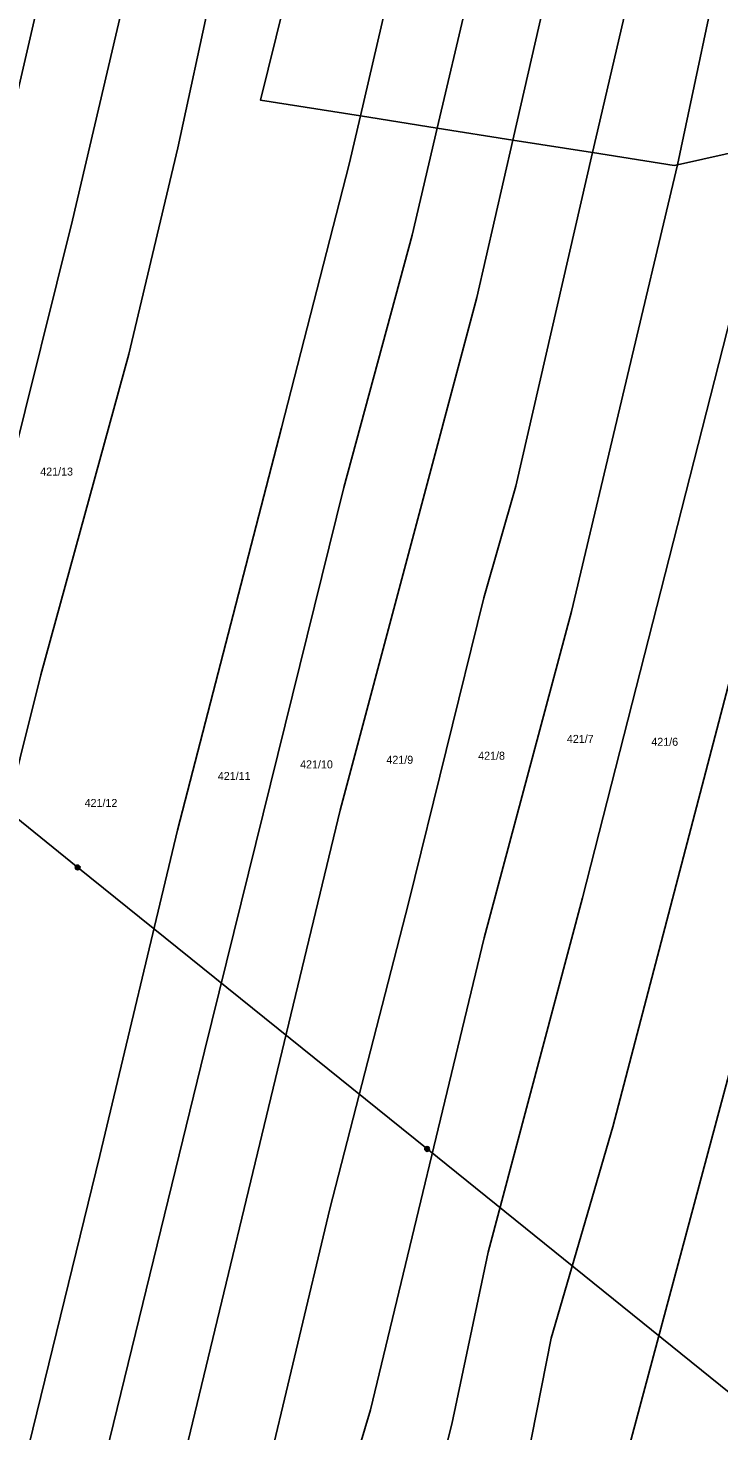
# Model space of a CAD drawing. Extents: x -757266 to -753360, y -1162585 to -1157740.
# Drawn here: x -754320 to -754173.3, y -1161339.7 to -1161041.7 of the extents above; entities that cross this region are included whole.
import ezdxf

# ---------------------------------------------------------------- set-up
doc = ezdxf.new("R2010")
doc.units = 0
for name, color, linetype in [('Hranice parcel', 7, 'Continuous'), ('Parcelní čísla', 7, 'Continuous'), ('Poz předměty', 7, 'Continuous')]:
    doc.layers.add(name, color=color, linetype=linetype)

msp = doc.modelspace()

# ---------------------------------------------------------------- linework, layer by layer
at = {"layer": 'Hranice parcel'}
for p, q in [((-754233.09, -1161062.92), (-754249.41, -1161060.34)), ((-754217.05, -1161065.46), (-754233.09, -1161062.92)), ((-754200.1, -1161068.14), (-754217.05, -1161065.46)), ((-754161.87, -1161066.18), (-754182.05, -1161070.71))]:
    msp.add_line(p, q, dxfattribs=at)
for points in [[(-754119.24, -1160813.08), (-754149.07, -1160933.43), (-754164.64, -1160995.63), (-754171.67, -1161021.51), (-754182.05, -1161070.71)], [(-754139.1, -1160824.77), (-754152.21, -1160879.84), (-754173.83, -1160958.14), (-754179.85, -1160982.04), (-754181.1, -1160989.94), (-754185.26, -1161004.29), (-754198.56, -1161061.46), (-754200.1, -1161068.14)], [(-754160.73, -1160838.86), (-754186.23, -1160938.4), (-754200.81, -1160994.66), (-754217.05, -1161065.46)], [(-754179.25, -1160846.93), (-754189.1, -1160890.03), (-754200.84, -1160928.27), (-754215.79, -1160985.35), (-754226.68, -1161035.55), (-754233.09, -1161062.92)], [(-754200.33, -1160854.21), (-754205.73, -1160882.26), (-754220.29, -1160934.88), (-754249.41, -1161060.34)], [(-754249.41, -1161060.34), (-754270.64, -1161056.98), (-754247.49, -1160963.34), (-754249.94, -1160940.51), (-754235.37, -1160867)], [(-754240.23, -1160869.33), (-754258.1, -1160934.43), (-754274.18, -1161002.2), (-754288.17, -1161067.13), (-754298.61, -1161110.97), (-754317.3, -1161179.08), (-754343.58, -1161284.28), (-754376.56, -1161413.76)], [(-754261.38, -1160876.02), (-754273.65, -1160920.93), (-754281.63, -1160958.76), (-754310.59, -1161082.5), (-754337.36, -1161190.1), (-754364.7, -1161299.26), (-754368.3, -1161317.87), (-754385.39, -1161380.66), (-754397.98, -1161421.24)], [(-754283.62, -1160882.92), (-754298.95, -1160954.38), (-754325.71, -1161070.45), (-754355.11, -1161191.34), (-754367.94, -1161239.65), (-754384.51, -1161312.03), (-754399.66, -1161368.8), (-754416.72, -1161429.57)], [(-754249.41, -1161060.34), (-754251.78, -1161070.56), (-754266.17, -1161126.61), (-754288.27, -1161212.11), (-754304.75, -1161281.16), (-754334.08, -1161400.67)], [(-754217.13, -1161361.64), (-754208.9, -1161319.99), (-754195.82, -1161275.12), (-754168.53, -1161170.95), (-754142.6, -1161061.86)], [(-754119.72, -1161060.47), (-754124.54, -1161081.93), (-754135.9, -1161126.37), (-754156.3, -1161212.19), (-754170.4, -1161261.14), (-754195.32, -1161354.12)], [(-754233.09, -1161062.92), (-754238.42, -1161085.66), (-754252.96, -1161139.29), (-754282.51, -1161259), (-754315.74, -1161394.89)], [(-754217.05, -1161065.46), (-754224.73, -1161098.93), (-754253.73, -1161207.84), (-754297.38, -1161389.11)], [(-754200.1, -1161068.14), (-754216.43, -1161139.01), (-754223.2, -1161162.75), (-754239.21, -1161227.62), (-754255.89, -1161292.52), (-754277.33, -1161382.62)], [(-754161.87, -1161066.18), (-754166.33, -1161085.43), (-754202.23, -1161226.42), (-754222.27, -1161301.71), (-754229.99, -1161338.26), (-754237.73, -1161368.75)], [(-754182.05, -1161070.71), (-754182.79, -1161070.88), (-754200.1, -1161068.14)], [(-754182.05, -1161070.71), (-754204.57, -1161165.62), (-754223.15, -1161234.96), (-754247.26, -1161335.2), (-754259.5, -1161376.33)]]:
    msp.add_lwpolyline(points, dxfattribs=at)
at = {"layer": 'Poz předměty'}
for p, q in [((-754373.71, -1161168.05), (-754309.46, -1161219.99)), ((-754309.46, -1161219.99), (-754235.25, -1161279.81)), ((-754235.25, -1161279.81), (-754166.74, -1161335.11))]:
    msp.add_line(p, q, dxfattribs=at)
for centre, radius in [((-754309.4634, -1161219.9899), 0.5), ((-754309.4634, -1161219.9899), 0.4), ((-754309.4634, -1161219.9899), 0.3), ((-754309.4634, -1161219.9899), 0.2), ((-754309.4634, -1161219.9899), 0.1), ((-754235.2534, -1161279.8099), 0.5), ((-754235.2534, -1161279.8099), 0.4), ((-754235.2534, -1161279.8099), 0.3), ((-754235.2534, -1161279.8099), 0.2), ((-754235.2534, -1161279.8099), 0.1)]:
    msp.add_circle(centre, radius, dxfattribs=at)

# ---------------------------------------------------------------- texts
at = {"layer": 'Parcelní čísla'}
for s, p in [('421/13', (-754317.41, -1161136.75)), ('421/7', (-754205.57, -1161193.54)), ('421/6', (-754187.64, -1161194.15)), ('421/9', (-754243.9, -1161197.97)), ('421/8', (-754224.41, -1161197.11)), ('421/10', (-754262.22, -1161198.95)), ('421/11', (-754279.7, -1161201.42)), ('421/12', (-754307.99, -1161207.15))]:
    msp.add_text(s, height=1.7, dxfattribs=at).set_placement(p)

doc.saveas('drawing.dxf')
